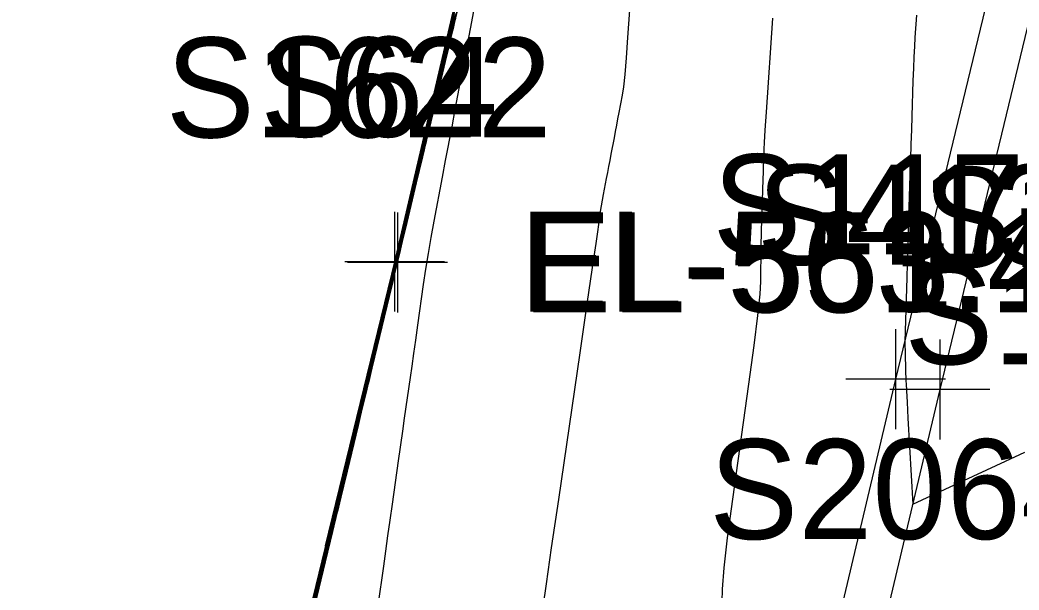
# Model space of a CAD drawing. Extents: x 1724534 to 1727318, y 657156 to 660047.
# Drawn here: x 1725433.66 to 1725473.69, y 659096.84 to 659119.65 of the extents above; entities that cross this region are included whole.
import ezdxf

# ---------------------------------------------------------------- set-up
doc = ezdxf.new("R2010")
doc.units = 0
for name, color, linetype in [('SURVEY - CONTOURS - Index with Text', 7, 'Continuous'), ('SURVEY - CONTOURS - Intermediate with optional Text', 7, 'Continuous'), ('SURVEY - DTM - Breaklines', 7, 'Continuous'), ('SURVEY - DTM - Breaklines - Points - Elevations', 7, 'Continuous'), ('SURVEY - DTM - Breaklines - Points - Locators', 7, 'Continuous'), ('SURVEY - DTM - Breaklines - Points - Numbers', 7, 'Continuous'), ('SURVEY - NON-TRANSPORTATION - Features', 7, 'Continuous'), ('SURVEY - NON-TRANSPORTATION - Features - Points - Elevations', 7, 'Continuous'), ('SURVEY - NON-TRANSPORTATION - Features - Points - Locators', 7, 'Continuous'), ('SURVEY - NON-TRANSPORTATION - Features - Points - Numbers', 7, 'Continuous'), ('SURVEY - TRANSPORTATION - Features', 7, 'Continuous'), ('SURVEY - TRANSPORTATION - Features - Points - Locators', 7, 'Continuous'), ('SURVEY - TRANSPORTATION - Features - Points - Numbers', 7, 'Continuous'), ('SURVEY - TRANSPORTATION - Roads - Points - Numbers', 7, 'Continuous'), ('SURVEY - UTILITIES - Electric (Lighting) - Points - Numbers', 7, 'Continuous')]:
    doc.layers.add(name, color=color, linetype=linetype)

msp = doc.modelspace()

# ---------------------------------------------------------------- linework, layer by layer
at = {"layer": 'SURVEY - CONTOURS - Index with Text'}
for points in [[(1725458.172, 659121.348), (1725458.005, 659118.953), (1725457.944, 659118.135), (1725457.886, 659117.477), (1725457.832, 659116.979), (1725457.781, 659116.64), (1725457.65, 659115.951), (1725457.602, 659115.694), (1725457.553, 659115.439), (1725457.506, 659115.187), (1725457.458, 659114.938), (1725457.333, 659114.278), (1725457.286, 659114.032), (1725457.24, 659113.788), (1725457.194, 659113.547), (1725457.149, 659113.308), (1725457.029, 659112.675), (1725456.986, 659112.44), (1725456.946, 659112.21), (1725456.91, 659111.984), (1725456.878, 659111.762), (1725456.796, 659111.177), (1725456.729, 659110.71), (1725456.589, 659109.748), (1725456.376, 659108.289), (1725456.089, 659106.336), (1725455.229, 659100.465), (1725454.944, 659098.52), (1725454.734, 659097.088), (1725454.6, 659096.168)], [(1725431.702, 659037.607), (1725434.483, 659051.964), (1725436.289, 659061.278), (1725436.739, 659062.97), (1725442.803, 659085.689), (1725443.218, 659087.406), (1725444.067, 659090.895), (1725444.533, 659092.814), (1725445.251, 659095.766), (1725445.721, 659097.707), (1725446.434, 659100.638), (1725446.909, 659102.599), (1725448.47, 659109.011), (1725448.782, 659110.316), (1725449.09, 659111.611), (1725449.912, 659115.124), (1725450.242, 659116.515), (1725451.057, 659119.996)], [(1725451.099, 659119.877), (1725451.021, 659119.546), (1725450.959, 659119.285), (1725450.756, 659118.418), (1725450.678, 659118.088), (1725450.583, 659117.688), (1725450.472, 659117.22), (1725450.152, 659115.88), (1725449.946, 659115.012), (1725449.868, 659114.68), (1725449.806, 659114.417), (1725449.663, 659113.807), (1725449.602, 659113.544), (1725449.523, 659113.213), (1725449.429, 659112.814), (1725449.318, 659112.348), (1725448.999, 659111.013), (1725448.894, 659110.574), (1725448.819, 659110.258), (1725448.757, 659109.996), (1725448.752, 659109.976), (1725448.735, 659109.906), (1725448.689, 659109.712), (1725448.612, 659109.394), (1725448.181, 659107.606), (1725448.068, 659107.136), (1725447.972, 659106.737), (1725447.892, 659106.408), (1725447.829, 659106.148), (1725447.629, 659105.326), (1725447.574, 659105.099), (1725447.518, 659104.871), (1725447.462, 659104.64), (1725447.312, 659104.024), (1725447.167, 659103.428), (1725447.071, 659103.03), (1725446.959, 659102.566), (1725446.64, 659101.239), (1725446.528, 659100.775), (1725446.352, 659100.045), (1725446.287, 659099.78), (1725446.137, 659099.162), (1725446.072, 659098.897), (1725445.992, 659098.566), (1725445.784, 659097.704), (1725445.465, 659096.379)]]:
    msp.add_lwpolyline(points, dxfattribs=at)
at = {"layer": 'SURVEY - CONTOURS - Intermediate with optional Text'}
for points in [[(1725445.903, 659098.605), (1725448.683, 659110.025), (1725452.148, 659124.837)], [(1725433.535, 659046.907), (1725434.2, 659050.332), (1725435.155, 659055.249), (1725436.189, 659060.571), (1725436.327, 659061.277), (1725436.987, 659063.76), (1725438.005, 659067.578), (1725440.668, 659077.564), (1725442.833, 659085.68), (1725443.42, 659088.113), (1725444.157, 659091.145), (1725444.604, 659092.998), (1725445.337, 659096.012), (1725445.887, 659098.289), (1725446.516, 659100.878), (1725447.07, 659103.169), (1725448.273, 659108.114), (1725448.778, 659110.212), (1725449.263, 659112.252), (1725449.964, 659115.239), (1725450.417, 659117.144), (1725451.112, 659120.109)], [(1725434.699, 659053.17), (1725436.273, 659061.292), (1725442.792, 659085.707), (1725443.255, 659087.615), (1725444.093, 659091.06), (1725445.284, 659095.959), (1725446.393, 659100.517), (1725447.219, 659103.916), (1725448.527, 659109.292), (1725448.791, 659110.394), (1725449.003, 659111.291), (1725449.936, 659115.274), (1725450.155, 659116.2), (1725451.081, 659120.153)], [(1725429.966, 659025.758), (1725430.741, 659031.202), (1725430.886, 659032.237), (1725431.415, 659035.966), (1725431.447, 659036.202), (1725431.482, 659036.4), (1725434.451, 659051.71), (1725436.305, 659061.264), (1725436.343, 659061.413), (1725437.366, 659065.246), (1725442.825, 659085.715), (1725443.319, 659087.759), (1725444.112, 659091.02), (1725444.618, 659093.111), (1725445.294, 659095.889), (1725445.804, 659097.998), (1725446.475, 659100.758), (1725446.99, 659102.884), (1725448.342, 659108.44), (1725448.764, 659110.197), (1725449.177, 659111.932), (1725449.938, 659115.182), (1725450.329, 659116.829), (1725451.085, 659120.053)], [(1725433.615, 659047.15), (1725434.133, 659049.808), (1725434.569, 659052.052), (1725435.237, 659055.483), (1725436.191, 659060.385), (1725436.361, 659061.256), (1725436.382, 659061.34), (1725437.317, 659064.857), (1725442.731, 659085.181), (1725442.862, 659085.671), (1725443.621, 659088.819), (1725444.146, 659090.979), (1725444.876, 659094.003), (1725445.422, 659096.257), (1725446.054, 659098.871), (1725446.599, 659101.119), (1725447.231, 659103.739), (1725448.137, 659107.462), (1725448.805, 659110.243), (1725449.518, 659113.238), (1725449.924, 659114.969), (1725450.672, 659118.118), (1725451.075, 659119.835)], [(1725438.109, 659067.9), (1725439.491, 659073.087), (1725440.683, 659077.555), (1725442.847, 659085.676), (1725443.52, 659088.466), (1725444.113, 659090.903), (1725444.702, 659093.344), (1725445.29, 659095.765), (1725445.97, 659098.58), (1725446.557, 659100.999), (1725447.151, 659103.454), (1725448.205, 659107.788), (1725448.792, 659110.227), (1725449.35, 659112.573), (1725449.901, 659114.925), (1725450.588, 659117.818), (1725451.051, 659119.793)], [(1725439.45, 659073.254), (1725442.778, 659085.717), (1725448.64, 659109.803), (1725448.917, 659110.971), (1725449.899, 659115.173), (1725450.169, 659116.318), (1725451.043, 659120.054)], [(1725451.123, 659119.92), (1725451.048, 659119.604), (1725450.997, 659119.386), (1725450.891, 659118.936), (1725450.84, 659118.718), (1725450.765, 659118.402), (1725450.545, 659117.477), (1725450.189, 659115.981), (1725450.067, 659115.469), (1725449.968, 659115.055), (1725449.893, 659114.739), (1725449.842, 659114.52), (1725449.736, 659114.068), (1725449.685, 659113.85), (1725449.61, 659113.534), (1725449.512, 659113.12), (1725449.39, 659112.609), (1725449.034, 659111.116), (1725448.917, 659110.625), (1725448.764, 659109.984), (1725448.761, 659109.969), (1725448.691, 659109.679), (1725448.605, 659109.324), (1725448.486, 659108.83), (1725448.124, 659107.325), (1725448, 659106.81), (1725447.9, 659106.396), (1725447.824, 659106.082), (1725447.772, 659105.867), (1725447.665, 659105.429), (1725447.625, 659105.264), (1725447.584, 659105.098), (1725447.392, 659104.308), (1725447.339, 659104.09), (1725447.263, 659103.774), (1725447.163, 659103.361), (1725447.04, 659102.851), (1725446.681, 659101.359), (1725446.558, 659100.849), (1725446.458, 659100.436), (1725446.382, 659100.121), (1725446.329, 659099.903), (1725446.22, 659099.453), (1725446.167, 659099.235), (1725446.091, 659098.92), (1725445.991, 659098.506), (1725445.868, 659097.995), (1725445.508, 659096.502)], [(1725451.147, 659119.962), (1725451.034, 659119.487), (1725450.965, 659119.192), (1725450.924, 659119.018), (1725450.751, 659118.288), (1725450.618, 659117.733), (1725450.225, 659116.082), (1725450.092, 659115.527), (1725449.99, 659115.098), (1725449.919, 659114.797), (1725449.878, 659114.623), (1725449.809, 659114.329), (1725449.768, 659114.155), (1725449.697, 659113.854), (1725449.595, 659113.425), (1725448.939, 659110.676), (1725448.847, 659110.288), (1725448.772, 659109.973), (1725448.769, 659109.963), (1725448.75, 659109.882), (1725448.693, 659109.646), (1725448.599, 659109.254), (1725448.467, 659108.708), (1725448.066, 659107.044), (1725447.931, 659106.484), (1725447.828, 659106.055), (1725447.756, 659105.756), (1725447.714, 659105.586), (1725447.646, 659105.307), (1725447.595, 659105.096), (1725447.569, 659104.989), (1725447.473, 659104.593), (1725447.431, 659104.421), (1725447.358, 659104.121), (1725447.255, 659103.692), (1725447.121, 659103.136), (1725446.722, 659101.48), (1725446.588, 659100.923), (1725446.485, 659100.496), (1725446.413, 659100.197), (1725446.372, 659100.026), (1725446.303, 659099.744), (1725446.262, 659099.574), (1725446.189, 659099.274), (1725445.951, 659098.286), (1725445.551, 659096.625)], [(1725451.102, 659119.718), (1725451.071, 659119.588), (1725451.039, 659119.448), (1725451.008, 659119.318), (1725450.94, 659119.031), (1725450.834, 659118.588), (1725450.691, 659117.989), (1725450.261, 659116.183), (1725450.118, 659115.584), (1725449.945, 659114.856), (1725449.914, 659114.726), (1725449.882, 659114.59), (1725449.851, 659114.461), (1725449.783, 659114.174), (1725449.535, 659113.131), (1725449.103, 659111.322), (1725448.962, 659110.728), (1725448.86, 659110.303), (1725448.799, 659110.048), (1725448.778, 659109.957), (1725448.757, 659109.87), (1725448.695, 659109.613), (1725448.592, 659109.185), (1725448.448, 659108.586), (1725447.863, 659106.159), (1725447.756, 659105.714), (1725447.687, 659105.43), (1725447.657, 659105.305), (1725447.628, 659105.185), (1725447.606, 659105.094), (1725447.595, 659105.048), (1725447.583, 659105.002), (1725447.553, 659104.878), (1725447.523, 659104.752), (1725447.347, 659104.023), (1725447.202, 659103.42), (1725446.763, 659101.6), (1725446.618, 659100.997), (1725446.512, 659100.555), (1725446.414, 659100.149), (1725446.386, 659100.035), (1725446.356, 659099.912), (1725446.288, 659099.628), (1725446.18, 659099.183), (1725445.594, 659096.747)], [(1725451.834, 659120.013), (1725451.7, 659119.305), (1725451.086, 659116.071), (1725450.956, 659115.384), (1725450.699, 659114.033), (1725450.573, 659113.369), (1725450.238, 659111.606), (1725450.118, 659110.951), (1725450.008, 659110.309), (1725449.907, 659109.679), (1725449.817, 659109.062), (1725449.59, 659107.432), (1725449.507, 659106.843), (1725449.43, 659106.298), (1725449.358, 659105.797), (1725449.291, 659105.339), (1725449.054, 659103.715), (1725448.98, 659103.199), (1725448.811, 659102.007), (1725448.567, 659100.275), (1725448.477, 659099.633), (1725448.388, 659099.005), (1725448.302, 659098.391), (1725448.218, 659097.791), (1725447.995, 659096.21)], [(1725463.814, 659119.722), (1725463.553, 659115.968), (1725463.505, 659115.249), (1725463.474, 659114.752), (1725463.46, 659114.479), (1725463.436, 659113.705), (1725463.43, 659113.521), (1725463.424, 659113.328), (1725463.407, 659112.8), (1725463.387, 659112.151), (1725463.379, 659111.91), (1725463.359, 659111.251), (1725463.352, 659111.034), (1725463.343, 659110.75), (1725463.343, 659110.742), (1725463.342, 659110.698), (1725463.341, 659110.572), (1725463.332, 659109.188), (1725463.3, 659108.683), (1725463.208, 659107.829), (1725463.057, 659106.626), (1725462.846, 659105.075), (1725462.204, 659100.476), (1725461.997, 659098.925), (1725461.858, 659097.722), (1725461.787, 659096.867), (1725461.784, 659096.361)], [(1725469.578, 659119.844), (1725469.515, 659118.948), (1725469.492, 659118.588), (1725469.471, 659118.179), (1725469.452, 659117.722), (1725469.435, 659117.216), (1725469.39, 659115.803), (1725469.373, 659115.259), (1725469.355, 659114.685), (1725469.336, 659114.082), (1725469.316, 659113.449), (1725469.262, 659111.722), (1725469.242, 659111.088), (1725469.223, 659110.478), (1725469.204, 659109.895), (1725469.187, 659109.336), (1725469.107, 659106.79), (1725469.138, 659105.702), (1725469.144, 659105.497), (1725469.149, 659105.351), (1725469.151, 659105.263), (1725469.152, 659105.232), (1725469.152, 659105.228), (1725469.152, 659105.225), (1725469.152, 659105.222), (1725469.153, 659105.217), (1725469.153, 659105.211), (1725469.153, 659105.194), (1725469.159, 659105.096), (1725469.174, 659104.816), (1725469.2, 659104.354), (1725469.235, 659103.709), (1725469.426, 659100.273), (1725473.144, 659101.988), (1725473.923, 659102.348)]]:
    msp.add_lwpolyline(points, dxfattribs=at)
at = {"layer": 'SURVEY - DTM - Breaklines'}
for points in [[(1725548.52, 659521.481), (1725540.965, 659497.216), (1725536.847, 659481.64), (1725536.065, 659476.4), (1725532.186, 659451.331), (1725527.526, 659426.779), (1725520.287, 659402.807), (1725512.005, 659379.174), (1725506.044, 659356.068), (1725503.268, 659330.772), (1725496.158, 659306.737), (1725491.301, 659280.213), (1725484.669, 659256.065), (1725478.26, 659232.056), (1725472.366, 659207.66), (1725466.542, 659183.359), (1725459.12, 659159.228), (1725454.379, 659134.473), (1725448.668, 659109.979), (1725442.764, 659085.69), (1725436.263, 659061.294), (1725431.444, 659036.269), (1725428.274, 659013.717), (1725429.417, 659007.151)], [(1725504.884, 659250.966), (1725498.725, 659226.793), (1725492.704, 659202.503), (1725486.609, 659178.27), (1725480.544, 659153.955), (1725474.624, 659129.616), (1725468.741, 659105.278), (1725462.975, 659080.964), (1725457.482, 659056.509), (1725452.226, 659031.922), (1725447.641, 659009.959), (1725446.425, 659003.851), (1725441.811, 658979.15), (1725437.527, 658954.376), (1725432.503, 658922.481), (1725434.197, 658921.722)]]:
    msp.add_lwpolyline(points, dxfattribs=at)
at = {"layer": 'SURVEY - DTM - Breaklines - Points - Locators'}
for p, q in [((1725448.668, 659111.979), (1725448.668, 659107.979)), ((1725450.668, 659109.979), (1725446.668, 659109.979)), ((1725468.741, 659107.278), (1725468.741, 659103.278)), ((1725470.741, 659105.278), (1725466.741, 659105.278))]:
    msp.add_line(p, q, dxfattribs=at)
at = {"layer": 'SURVEY - NON-TRANSPORTATION - Features'}
msp.add_lwpolyline([(1725429.417, 659007.151), (1725429.417, 659007.151), (1725428.421, 659013.689), (1725431.524, 659036.252), (1725436.426, 659061.257), (1725442.928, 659085.652), (1725448.785, 659109.952), (1725454.62, 659134.415), (1725460.644, 659158.853), (1725466.906, 659183.267), (1725472.478, 659207.631), (1725478.626, 659231.962), (1725484.871, 659256.014)], dxfattribs=at)
at = {"layer": 'SURVEY - NON-TRANSPORTATION - Features - Points - Locators'}
for p, q in [((1725448.785, 659111.952), (1725448.785, 659107.952)), ((1725450.785, 659109.952), (1725446.785, 659109.952))]:
    msp.add_line(p, q, dxfattribs=at)
at = {"layer": 'SURVEY - TRANSPORTATION - Features'}
msp.add_lwpolyline([(1725506.673, 659250.514), (1725500.512, 659226.334), (1725494.493, 659202.049), (1725488.389, 659177.819), (1725482.327, 659153.516), (1725476.395, 659129.191), (1725470.514, 659104.862), (1725464.748, 659080.55), (1725459.259, 659056.109), (1725454.008, 659031.549), (1725449.429, 659009.612), (1725448.213, 659003.504), (1725443.603, 658978.829), (1725439.325, 658954.082), (1725434.304, 658922.209), (1725434.197, 658921.722)], dxfattribs=at)
at = {"layer": 'SURVEY - TRANSPORTATION - Features - Points - Locators'}
for p, q in [((1725470.514, 659106.862), (1725470.514, 659102.862)), ((1725472.514, 659104.862), (1725468.514, 659104.862))]:
    msp.add_line(p, q, dxfattribs=at)

# ---------------------------------------------------------------- texts
at = {"layer": 'SURVEY - DTM - Breaklines - Points - Elevations'}
msp.add_text('EL-563.44', height=4, dxfattribs=at).set_placement((1725453.668, 659107.979))
at = {"layer": 'SURVEY - DTM - Breaklines - Points - Numbers'}
for s, p in [('S64', (1725443.284, 659114.979)), ('S117', (1725461.405, 659110.278))]:
    msp.add_text(s, height=4, dxfattribs=at).set_placement(p)
at = {"layer": 'SURVEY - NON-TRANSPORTATION - Features - Points - Elevations'}
msp.add_text('EL-551.17', height=4, dxfattribs=at).set_placement((1725453.785, 659107.952))
at = {"layer": 'SURVEY - NON-TRANSPORTATION - Features - Points - Numbers'}
msp.add_text('S1622', height=4, dxfattribs=at).set_placement((1725439.497, 659114.952))
at = {"layer": 'SURVEY - TRANSPORTATION - Features - Points - Numbers'}
msp.add_text('S413', height=4, dxfattribs=at).set_placement((1725463.178, 659109.862))
at = {"layer": 'SURVEY - TRANSPORTATION - Roads - Points - Numbers'}
for s, p in [('S1380', (1725469.845, 659109.764)), ('S1379', (1725469.09, 659105.872))]:
    msp.add_text(s, height=4, dxfattribs=at).set_placement(p)
at = {"layer": 'SURVEY - UTILITIES - Electric (Lighting) - Points - Numbers'}
msp.add_text('S2064', height=4, dxfattribs=at).set_placement((1725461.272, 659098.875))

doc.saveas('drawing.dxf')
